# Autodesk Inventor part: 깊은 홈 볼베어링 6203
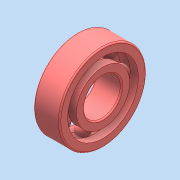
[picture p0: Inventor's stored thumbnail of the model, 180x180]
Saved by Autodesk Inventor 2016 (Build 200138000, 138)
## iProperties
Created: 2024-09
Part Number: 깊은 홈 볼베어링 6203
Material: 일반
Description: 깊은 그루브 볼 베어링
Document SubType Name: Modeling
Designer: pc-7
Density: 1 g/cm^3
Appearance: 기본값
Author: jhkim
Sending System: Autodesk Inventor 2025
Preprocessor: ST-DEVELOPER v20
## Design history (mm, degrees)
node "깊은 홈 볼베어링 62031"
node "솔리드1"
node "솔리드2"
node "솔리드3"
node "솔리드4"
node "솔리드5"
node "솔리드6"
node "솔리드7"
node "솔리드8"
node "솔리드9"
body "Solid1"
node "Solid1:1"
node "Solid1:2"
node "Solid1:3"
node "Solid1:4"
node "Solid1:5"
node "Solid1:6"
node "Solid1:7"
node "Solid1:8"
